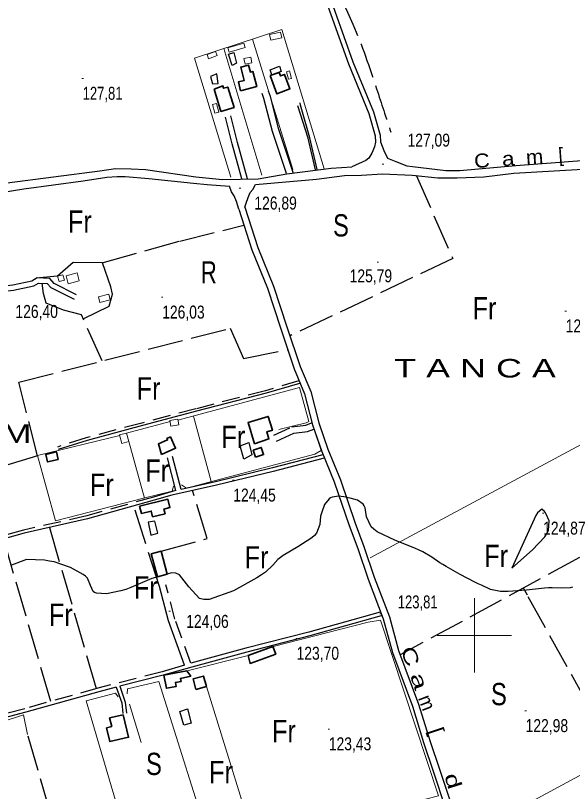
# Model space of a CAD drawing. Extents: x 483855 to 488461, y 4388206 to 4391419.
# Drawn here: x 484691 to 485066, y 4389395 to 4389918 of the extents above; entities that cross this region are included whole.
import ezdxf
from ezdxf.enums import TextEntityAlignment as Align

# ---------------------------------------------------------------- set-up
doc = ezdxf.new("R2010")
doc.units = 0
doc.header["$LTSCALE"] = 4
doc.linetypes.add('LONG_DASHED', pattern=[7.5, 6, -1.5])
doc.linetypes.add('MEDIUM_DASHED', pattern=[4.5, 3, -1.5])
for name, color, linetype, lineweight in [('1', 7, 'Continuous', 13), ('21', 7, 'Continuous', 25), ('25', 7, 'LONG_DASHED', 25), ('36', 7, 'Continuous', 25), ('38', 7, 'Continuous', 25), ('47', 7, 'Continuous', 35), ('51', 7, 'Continuous', 13), ('7', 7, 'Continuous', 13), ('8', 7, 'Continuous', 25)]:
    doc.layers.add(name, color=color, linetype=linetype, lineweight=lineweight)
doc.layers.add('31', color=7, linetype='Continuous')
doc.layers.add('5', color=7, linetype='Continuous')

msp = doc.modelspace()

# ---------------------------------------------------------------- linework, layer by layer
at = {"layer": '1'}
for p, q in [((485000, 4389525), (485000, 4389475)), ((484975, 4389500), (485025, 4389500))]:
    msp.add_line(p, q, dxfattribs=at)
at = {"layer": '21'}
for points in [[(484836.87, 4389884.29), (484834.31, 4389892.08), (484837.91, 4389893.06), (484839.72, 4389885.87)], [(484862.49, 4389881.49), (484868.6, 4389883.89), (484869.79, 4389880.24), (484863.59, 4389877.95)], [(484827.44, 4389872.27), (484826.53, 4389878.72), (484822.18, 4389876.99), (484823.54, 4389871.96)], [(484844.73, 4389618.9), (484842.17, 4389627.75), (484848.01, 4389630.08), (484850.05, 4389621.76), (484850.05, 4389621.76)], [(484786.68, 4389568.99), (484784.64, 4389577.09), (484780.14, 4389576.26), (484782.1, 4389567.64)], [(484804.29, 4389439.4), (484801.43, 4389448.77), (484806.6, 4389450.43), (484809.24, 4389440.83)]]:
    msp.add_lwpolyline(points, close=True, dxfattribs=at)
at = {"layer": '25'}
for p, q in [((484705.72, 4389621.08), (484590.86, 4389586.38)), ((484787.79, 4389533.04), (484770.53, 4389587.41)), ((484713.69, 4389572.84), (484745.12, 4389464.08)), ((484682.67, 4389565.03), (484714.45, 4389455.44)), ((484731.26, 4389322.59), (484698.98, 4389433.23))]:
    msp.add_line(p, q, dxfattribs=at)
for points in [[(484960.69, 4389810.47), (484985.39, 4389754.23), (484875.77, 4389701.96)], [(484749.18, 4389751.14), (484801.43, 4389765.93), (484844.74, 4389776.57)], [(484736.52, 4389713.52), (484753.95, 4389722.12), (484756.18, 4389730.22), (484755.13, 4389734.95), (484749.4, 4389751.14), (484729.59, 4389751.41), (484719.18, 4389742.24), (484707.06, 4389741.02)], [(484749.32, 4389685.15), (484735.35, 4389716.09), (484723.27, 4389719.37), (484711.56, 4389724.15), (484709.67, 4389730.6), (484708.76, 4389737.5)], [(484705.67, 4389621.07), (484692.97, 4389670.79), (484835.51, 4389707.1), (484844.32, 4389686.64), (484874.23, 4389692.61)], [(485120.83, 4389655.04), (485149.85, 4389595.39), (484950.04, 4389486.85)], [(484788.87, 4389556.85), (484819.92, 4389565.3), (484810.15, 4389597.68)], [(485096.79, 4389419.39), (485091.62, 4389426.29), (485035.72, 4389527.02), (485033.06, 4389531.95)]]:
    msp.add_lwpolyline(points, dxfattribs=at)
at = {"layer": '36'}
for points in [[(484899.96, 4389938.26), (484918.17, 4389886.74), (484932, 4389853.13), (484936.44, 4389837.39), (484936.77, 4389832.92)], [(484896.84, 4389937.13), (484915.07, 4389885.55), (484928.86, 4389852.04), (484933.16, 4389836.82), (484933.46, 4389832.68)], [(484954.49, 4389816.61), (484958.29, 4389816.26), (484980.8, 4389813.41), (484990.19, 4389813.57), (485027.83, 4389816.84), (485090.06, 4389821.6), (485142.59, 4389825.05), (485187.89, 4389829.45), (485220.96, 4389835.04), (485245.06, 4389840.2), (485275.43, 4389846.23), (485289.35, 4389849.97), (485323.18, 4389862.3), (485378.61, 4389883.94), (485426.84, 4389904.19), (485462.15, 4389918.62)], [(484933.46, 4389832.68), (484932.68, 4389829.38), (484930.81, 4389825.18), (484928.94, 4389821.8), (484926.77, 4389820.15), (484917.42, 4389816.09)], [(484936.77, 4389832.92), (484938.91, 4389826.92), (484941.54, 4389821.82), (484947.17, 4389819.58), (484954.49, 4389816.61)], [(484517.17, 4389784.19), (484603.13, 4389794.82), (484685.32, 4389805.3), (484747.71, 4389813.3), (484758.15, 4389814.9), (484768.74, 4389814.74), (484778.42, 4389814.15), (484812.37, 4389809.26), (484830.33, 4389807.54), (484854.35, 4389807.87), (484873.69, 4389811.22), (484903.58, 4389815.06), (484917.42, 4389816.09)], [(484852.62, 4389804.05), (484865.36, 4389805.27), (484893.56, 4389807.56), (484912.46, 4389810.07), (484923.86, 4389810.31), (484938.18, 4389811.24), (484958.14, 4389810.37), (484975.32, 4389808.52), (484988.45, 4389808.47), (485006.45, 4389809.17), (485026.55, 4389811.61), (485084.76, 4389815.15)], [(484299.08, 4389757.16), (484317.53, 4389757.41), (484351.51, 4389761.97), (484377.46, 4389764.71), (484402.58, 4389767.45), (484445.48, 4389770.82), (484494.53, 4389776), (484517.86, 4389778.97), (484559.03, 4389783.09), (484594.28, 4389787.27), (484623.68, 4389791.07), (484655.71, 4389794.72), (484696.36, 4389801.24), (484736.4, 4389806.63), (484752.3, 4389808.91), (484759.43, 4389809.37), (484764.68, 4389809.45), (484780.66, 4389808.05), (484810.67, 4389804.88), (484820.05, 4389804.07), (484834.9, 4389802.84)], [(484841.23, 4389787.52), (484839.72, 4389792.7), (484838.14, 4389796.45), (484836.26, 4389799.14), (484834.9, 4389802.84)], [(484845.4, 4389788.86), (484846.17, 4389791.51), (484847.52, 4389795.41), (484849.01, 4389798.71), (484850.74, 4389800.74), (484852.62, 4389804.05)], [(484841.23, 4389787.52), (484850.05, 4389760.01), (484860.52, 4389734.07), (484869.57, 4389706.78), (484878.46, 4389679.72), (484885.54, 4389663), (484890.98, 4389642), (484897.16, 4389624.09), (484905.59, 4389603.47), (484915.62, 4389574.16), (484921.35, 4389558.56), (484928.36, 4389537.87), (484938.6, 4389511.11), (484944.79, 4389488.39), (484958.28, 4389452.25), (484965.74, 4389427.66), (484972.45, 4389407.79), (484980.37, 4389383.88)], [(484845.4, 4389788.86), (484854.17, 4389761.5), (484864.63, 4389735.58), (484873.73, 4389708.15), (484882.56, 4389681.26), (484889.7, 4389664.41), (484895.18, 4389643.27), (484901.26, 4389625.63), (484909.69, 4389605.01), (484919.75, 4389575.62), (484925.48, 4389560.02), (484932.48, 4389539.36), (484942.77, 4389512.47), (484948.96, 4389489.73), (484962.43, 4389453.65), (484969.91, 4389429), (484976.6, 4389409.18), (484984.48, 4389385.4)]]:
    msp.add_lwpolyline(points, dxfattribs=at)
at = {"layer": '38'}
for p, q in [((484798.94, 4389597.61), (484793.2, 4389619.64)), ((484802.38, 4389598.39), (484796.61, 4389620.53)), ((484804.59, 4389479.91), (484789.67, 4389475.49)), ((484790.28, 4389473.12), (484761.11, 4389465.67))]:
    msp.add_line(p, q, dxfattribs=at)
for points in [[(484873.39, 4389811.39), (484863.95, 4389839.85), (484858.21, 4389862.12), (484856.93, 4389865.49)], [(484878.16, 4389811.52), (484868.33, 4389841.14), (484862.57, 4389863.51), (484861.2, 4389867.11)], [(484894.09, 4389814.3), (484889.17, 4389835.56), (484882.77, 4389857.51), (484882.53, 4389859.05)], [(484892.9, 4389813.93), (484887.96, 4389835.23), (484880.95, 4389857.13), (484880.95, 4389857.13)], [(484843.2, 4389807.94), (484836.88, 4389831.48), (484832.28, 4389849.55)], [(484847.12, 4389807.82), (484840.5, 4389832.43), (484835.91, 4389850.47)], [(484642.38, 4389793.03), (484646.2, 4389778.66), (484648.33, 4389763.52), (484650.51, 4389756.85), (484652.02, 4389752.79), (484652.18, 4389749.63), (484652.11, 4389744.76), (484651.82, 4389737.71), (484651.83, 4389733.13), (484652.06, 4389730.09), (484657.57, 4389726.68), (484661.06, 4389726.76), (484677.56, 4389731.52), (484689.56, 4389732.89), (484703.11, 4389735.76), (484706.27, 4389737.64), (484712.24, 4389737.27), (484714.66, 4389734.57), (484730.41, 4389726.64)], [(484731.95, 4389729.7), (484716.78, 4389737.33), (484713.85, 4389740.59), (484705.43, 4389741.12), (484701.85, 4389738.98), (484689.01, 4389736.27), (484676.88, 4389734.88), (484673.95, 4389734.04)], [(484882.23, 4389669.89), (484859.66, 4389663.33), (484812.87, 4389651.1), (484776.28, 4389641.52), (484739.02, 4389631.48), (484719.6, 4389625.37)], [(484866.69, 4389630.94), (484878.23, 4389636.28), (484887.61, 4389637.42), (484891.81, 4389639.01)], [(484898.87, 4389619.5), (484864.49, 4389610.63), (484826.16, 4389601.26), (484796.26, 4389594.55), (484784.24, 4389591.26)], [(484897.89, 4389621.73), (484863.9, 4389612.97), (484825.61, 4389603.6), (484802.38, 4389598.39)], [(484798.94, 4389597.61), (484795.59, 4389596.86), (484783.69, 4389593.21)], [(484784.24, 4389591.26), (484739.41, 4389578.66), (484696.74, 4389568.99), (484662.17, 4389559.25), (484634.72, 4389552.08), (484602.79, 4389543.7), (484577.66, 4389538.64), (484565.64, 4389534.57)], [(484804.59, 4389479.91), (484793.99, 4389509.73), (484787.79, 4389533.04)], [(484936.49, 4389515.75), (484888.52, 4389502.24), (484846.09, 4389491.31), (484808.84, 4389481.17)], [(484937.22, 4389513.16), (484889.22, 4389499.64), (484846.78, 4389488.7), (484809.6, 4389478.59), (484790.28, 4389473.12)], [(484758.75, 4389465.06), (484746.86, 4389462.02), (484697.81, 4389448.21), (484668.8, 4389440.59), (484635.36, 4389431.08)], [(484758.75, 4389465.06), (484762.41, 4389454.45), (484763.25, 4389447.34)]]:
    msp.add_lwpolyline(points, dxfattribs=at)
at = {"layer": '38', "linetype": 'MEDIUM_DASHED'}
for points in [[(484881.74, 4389671.57), (484859.19, 4389665.02), (484812.43, 4389652.8), (484775.83, 4389643.21), (484738.53, 4389633.16), (484719.07, 4389627.04)], [(484864.8, 4389635.01), (484876.99, 4389640.65), (484886.53, 4389641.81), (484890.32, 4389643.25)], [(484783.69, 4389593.21), (484738.91, 4389580.63), (484696.24, 4389570.96), (484661.64, 4389561.21), (484634.21, 4389554.04), (484606.45, 4389546.77)], [(484808.84, 4389481.17), (484798.22, 4389511.04), (484792.08, 4389534.18)], [(484789.67, 4389475.49), (484746.22, 4389464.38), (484697.17, 4389450.57), (484668.16, 4389442.95), (484634.69, 4389433.43)], [(484761.11, 4389465.67), (484764.8, 4389454.99), (484765.67, 4389447.63)]]:
    msp.add_lwpolyline(points, dxfattribs=at)
at = {"layer": '38', "linetype": 'LONG_DASHED'}
msp.add_spline([(484847.8, 4390081.07), (484852.23, 4390081.15), (484863.03, 4390080.87), (484863.11, 4390077.34), (484862.45, 4390068.71), (484862.46, 4390061.81), (484863.67, 4390053.19), (484866.01, 4390046.14), (484870.23, 4390036.09), (484878.06, 4390020.28), (484888.14, 4390001.02), (484892, 4389979.12), (484918.14, 4389912.17), (484934.11, 4389868.54), (484943.69, 4389839.3)], degree=3, dxfattribs=at)
at = {"layer": '47', "lineweight": 13}
for points in [[(484862.87, 4389901.43), (484870.3, 4389903.09), (484869.46, 4389906.84), (484862.03, 4389905.18)], [(484844.65, 4389899.45), (484833.86, 4389896.2), (484834.76, 4389893.21), (484845.55, 4389896.46)], [(484825.6, 4389893.72), (484819.9, 4389891.66), (484820.89, 4389888.91), (484826.59, 4389890.97)], [(484850.15, 4389886.11), (484849.35, 4389890.04), (484844.74, 4389889.1), (484845.54, 4389885.17)], [(484876.79, 4389875.57), (484875.51, 4389880.67), (484873.41, 4389880.14), (484874.69, 4389875.04)], [(484825.07, 4389852.24), (484823.62, 4389857.94), (484826.26, 4389858.61), (484827.71, 4389852.91)], [(484726.32, 4389737.08), (484733.73, 4389739.01), (484732.31, 4389744.44), (484724.9, 4389742.51)], [(484723.76, 4389739.62), (484722.73, 4389743.25), (484719.18, 4389742.24), (484720.21, 4389738.61)], [(484747.64, 4389724.58), (484754.6, 4389726.38), (484753.63, 4389730.15), (484746.67, 4389728.35)], [(484794.8, 4389644.92), (484800.16, 4389645.84), (484800.81, 4389642.01), (484795.45, 4389641.09)], [(484762.42, 4389629.42), (484760.91, 4389635.22), (484765.71, 4389636.47), (484767.22, 4389630.67)]]:
    msp.add_lwpolyline(points, close=True, dxfattribs=at)
at = {"layer": '47'}
for points in [[(484842.37, 4389867.19), (484853.4, 4389870.13), (484850.69, 4389880.29), (484849.07, 4389879.87), (484847.85, 4389884.57), (484842.58, 4389883.23), (484844.87, 4389874.21), (484841.02, 4389873.25)], [(484862.39, 4389877.5), (484866.98, 4389865.21), (484875.68, 4389868.48), (484871.99, 4389878.28), (484869.39, 4389877.3), (484868.47, 4389879.71)], [(484824.67, 4389868.36), (484829.27, 4389853.37), (484838.09, 4389856.1), (484833.85, 4389869.79), (484831.07, 4389868.94), (484830.56, 4389870.59)], [(484851.77, 4389629.19), (484847.47, 4389643.58), (484861.12, 4389647.66), (484863.89, 4389638.36), (484860.22, 4389637.29), (484861.6, 4389632.53)], [(484789.14, 4389621.88), (484798.66, 4389626.17), (484795.18, 4389633.86), (484792.87, 4389632.82), (484793.32, 4389631.8), (484787.11, 4389629.07)], [(484719.68, 4389618.69), (484712.41, 4389616.97), (484711.2, 4389622.06), (484718.47, 4389623.78)], [(484852.61, 4389620.11), (484857.98, 4389621.94), (484856.35, 4389626.72), (484850.98, 4389624.89)], [(484774.42, 4389587.13), (484793.54, 4389591.81), (484794.91, 4389586.17), (484790.87, 4389585.19), (484791.63, 4389582.01), (484783.15, 4389579.98), (484782.23, 4389583.8), (484775.61, 4389582.2)], [(484786.5, 4389539.59), (484782.28, 4389555.05), (484788.87, 4389556.85), (484793.09, 4389541.39)], [(484847.65, 4389486.5), (484864.29, 4389492.61), (484866.21, 4389487.36), (484848.92, 4389481.05)], [(484806.33, 4389476.08), (484790.81, 4389473.13), (484792.48, 4389464.32), (484799.12, 4389465.61), (484798.6, 4389468.25), (484802.36, 4389469), (484801.95, 4389471.02), (484808.91, 4389472.44)], [(484812.28, 4389463.57), (484819.44, 4389465.45), (484817.59, 4389472.5), (484810.43, 4389470.62)], [(484763.47, 4389446.31), (484767.02, 4389431.31), (484754.42, 4389428.34), (484752.23, 4389437.61), (484755.63, 4389438.44), (484754.17, 4389444.39)]]:
    msp.add_lwpolyline(points, close=True, dxfattribs=at)
at = {"layer": '51'}
for p, q in [((484850.44, 4389902.08), (484877.72, 4389814.21)), ((484831.12, 4389895.75), (484856.72, 4389810.28)), ((484765.71, 4389636.47), (484794.93, 4389644.23)), ((484822.55, 4389603.7), (484810.66, 4389647.92)), ((484767.22, 4389630.67), (484777.84, 4389592.64)), ((484847.65, 4389486.5), (484806.39, 4389476.01)), ((484819.44, 4389465.45), (484852.89, 4389357.84)), ((484767.74, 4389453.67), (484775.43, 4389427.65))]:
    msp.add_line(p, q, dxfattribs=at)
for points in [[(484835.87, 4389809.04), (484811.51, 4389889.34), (484870.29, 4389908.57), (484898.87, 4389814.7)], [(485208.27, 4389698.11), (485147.63, 4389669.43), (484929.68, 4389552.35)], [(484800.28, 4389645.13), (484882.08, 4389667.12), (484888.42, 4389644.25), (484886.62, 4389643.42), (484868.25, 4389638.89)], [(484797.35, 4389600.67), (484796.46, 4389597.29), (484778.01, 4389592.68), (484717.8, 4389577.36), (484705.65, 4389621.3), (484761.05, 4389634.73)], [(484891.96, 4389638.63), (484896.71, 4389624.68), (484892.59, 4389622.13), (484805.98, 4389599.33), (484802.68, 4389601.58)], [(484995.85, 4389364.85), (485120.04, 4389431.96), (485211.4, 4389479.07), (485268.52, 4389506.17), (485302.1, 4389523.63)], [(484760, 4389458.53), (484758.2, 4389461.08), (484738.48, 4389455.87), (484774.01, 4389335.08), (484925.98, 4389378.92), (484975.85, 4389391.9), (484936.8, 4389510.2), (484928.48, 4389508.92), (484864.34, 4389492.47)], [(484766, 4389460.49), (484766.22, 4389463.94), (484787.37, 4389468.85), (484824.91, 4389349.76)], [(484679.1, 4389437.17), (484680.37, 4389441.22), (484696.11, 4389446.5), (484698.98, 4389433.23)]]:
    msp.add_lwpolyline(points, dxfattribs=at)
at = {"layer": '7'}
for p, q in [((484735.57, 4389875.57), (484736.57, 4389875.57)), ((484937.9, 4389817.69), (484938.9, 4389817.69)), ((484841.61, 4389801.55), (484842.61, 4389801.55)), ((484934.41, 4389751.75), (484935.41, 4389751.75)), ((484789.14, 4389728.03), (484790.14, 4389728.03)), ((485061.01, 4389718.72), (485062.01, 4389718.72)), ((484837.05, 4389604.63), (484838.05, 4389604.63)), ((485045.78, 4389582.32), (485046.78, 4389582.32)), ((484794.22, 4389516.42), (484795.22, 4389516.42)), ((484936.37, 4389514.48), (484937.37, 4389514.48)), ((484879.69, 4389497.96), (484880.69, 4389497.96)), ((485034, 4389449.15), (485035, 4389449.15)), ((484901.39, 4389436.86), (484902.39, 4389436.86))]:
    msp.add_line(p, q, dxfattribs=at)
at = {"layer": '8'}
for points in [[(484976.74, 4389549), (484971.38, 4389552.73), (484965.18, 4389556.4), (484962.69, 4389557.58), (484959.86, 4389558.83), (484946.83, 4389563.95), (484934.58, 4389569.81), (484932.24, 4389571.53), (484930.36, 4389573.3), (484927.37, 4389580.03), (484926.41, 4389586), (484925.81, 4389587.29), (484925.07, 4389588.41), (484921.17, 4389591.12), (484916.3, 4389592.54), (484914.94, 4389592.85), (484913.58, 4389593.12), (484908.62, 4389593.8), (484904.13, 4389593.21), (484903.06, 4389592.68), (484902.06, 4389591.99), (484899.09, 4389588.19), (484897.1, 4389583.2), (484896.72, 4389581.76), (484896.41, 4389580.29), (484895.93, 4389574.8), (484893.65, 4389569.03), (484892.2, 4389567.4), (484890.4, 4389565.74), (484880.97, 4389559.63), (484871.26, 4389553.95), (484869.29, 4389552.57), (484867.62, 4389551.27), (484864.19, 4389547.3), (484859.25, 4389542.58), (484856.64, 4389540.8), (484853.49, 4389538.83), (484837.62, 4389530.04), (484821.23, 4389524.29), (484817.76, 4389524.24), (484814.74, 4389524.85), (484807.67, 4389532.64), (484801.36, 4389540.92), (484798.82, 4389541.85), (484795.93, 4389542.19), (484793.09, 4389541.39)], [(484793.09, 4389541.39), (484782.64, 4389538.47), (484768.51, 4389532.25), (484765.1, 4389531.01), (484761.9, 4389529.98), (484752.14, 4389528), (484745.41, 4389528.49), (484744.13, 4389529.01), (484743.1, 4389529.7), (484741.45, 4389533.59), (484739.37, 4389538.5), (484738.06, 4389539.84), (484736.42, 4389541.17), (484727.88, 4389545.87), (484716.86, 4389549.51), (484713.67, 4389550.16), (484710.42, 4389550.66), (484698.19, 4389551.17), (484688.03, 4389547.45)], [(485066.16, 4389532.51), (485064.41, 4389532.13), (485058.92, 4389531.92), (485052.3, 4389532.13), (485049.85, 4389532.02), (485047.12, 4389531.84), (485035, 4389530.59), (485022.85, 4389529.59), (485020.1, 4389529.58), (485017.62, 4389529.68), (485010.89, 4389530.98), (485004.73, 4389533.77), (485002.61, 4389534.81), (485000.3, 4389535.97), (484990.5, 4389541.11), (484980.89, 4389546.48), (484978.71, 4389547.78), (484976.74, 4389549)]]:
    msp.add_lwpolyline(points, dxfattribs=at)
msp.add_lwpolyline([(485025.32, 4389545.33), (485039.1, 4389557.67), (485047.39, 4389566.54), (485048.79, 4389568.71), (485049.81, 4389570.76), (485050.3, 4389577.14), (485048.32, 4389581.77), (485047.79, 4389582.72), (485047.26, 4389583.53), (485045.42, 4389585.22), (485042.6, 4389582.7), (485041.47, 4389580.84), (485040.17, 4389578.48)], close=True, dxfattribs=at)

# ---------------------------------------------------------------- texts
at = {"layer": '31'}
for s, width, p in [('Fr', 0.85, (484734.22, 4389771.6)), ('S', 0.8, (484910.09, 4389769.02)), ('R', 0.75, (484821.03, 4389737.34)), ('Fr', 0.85, (485006.81, 4389713.1)), ('Fr', 0.85, (484780.5, 4389659.05)), ('Fr', 0.85, (484837.57, 4389626.36)), ('Fr', 0.85, (484786.28, 4389603.64)), ('Fr', 0.85, (484749.03, 4389594.07)), ('Fr', 0.85, (485014.64, 4389546.09)), ('Fr', 0.85, (484853.25, 4389545.16)), ('Fr', 0.85, (484778.55, 4389524.86)), ('Fr', 0.85, (484721.36, 4389506.41)), ('S', 0.8, (485016.49, 4389452.89)), ('Fr', 0.85, (484871.7, 4389427.97)), ('S', 0.8, (484784.09, 4389405.83)), ('Fr', 0.85, (484829.27, 4389400.29))]:
    msp.add_text(s, height=15, dxfattribs=dict(at, width=width)).set_placement(p, align=Align.CENTER)
at = {"layer": '5'}
msp.add_text('[', height=9.49, rotation=4.167, dxfattribs=at).set_placement((485058.58, 4389819.35), align=Align.CENTER)
for s, rotation, width, p in [('C', 4.167, 1.15, (485005.38, 4389815.49)), ('a', 4.167, 1.2, (485023.08, 4389816.76)), ('m', 4.167, 1.1, (485040.85, 4389818.07)), ('C', 290.325, 1.45, (484952.39, 4389484.25)), ('a', 288.9, 1.6, (484958.34, 4389467.67)), ('m', 291.231, 0.95, (484963.63, 4389452.97)), ('[', 288.665, 1.2, (484970.13, 4389434.11)), ('d', 287.538, 1.5, (484981.15, 4389400.41))]:
    msp.add_text(s, height=9.49, rotation=rotation, dxfattribs=dict(at, width=width)).set_placement(p, align=Align.CENTER)
at = {"layer": '5', "width": 1.45}
msp.add_text('T A N C A   G R A N', height=12.49, dxfattribs=at).set_placement((485165.25, 4389673.92), align=Align.RIGHT)
msp.add_text('S O N   C O L O M', height=12.49, dxfattribs=at).set_placement((484499.75, 4389629.85))
at = {"layer": '7'}
for s, width, p in [('127,81', 0.75, (484736.07, 4389861.2)), ('127,09', 0.8, (484954.92, 4389829.62)), ('126,89', 0.8, (484851.74, 4389787.18)), ('125,79', 0.8, (484915.94, 4389738.11)), ('126,40', 0.8, (484690.78, 4389714.07)), ('126,03', 0.8, (484789.64, 4389713.66)), ('126,28', 0.8, (485061.51, 4389704.35)), ('124,45', 0.8, (484837.55, 4389590.26)), ('124,87', 0.8, (485046.28, 4389567.95)), ('123,81', 0.75, (484948.37, 4389518.19)), ('124,06', 0.8, (484805.84, 4389505.09)), ('123,70', 0.8, (484880.19, 4389483.59)), ('122,98', 0.8, (485034.5, 4389434.78)), ('123,43', 0.8, (484901.89, 4389422.49))]:
    msp.add_text(s, height=8.75, dxfattribs=dict(at, width=width)).set_placement(p)

doc.saveas('drawing.dxf')
